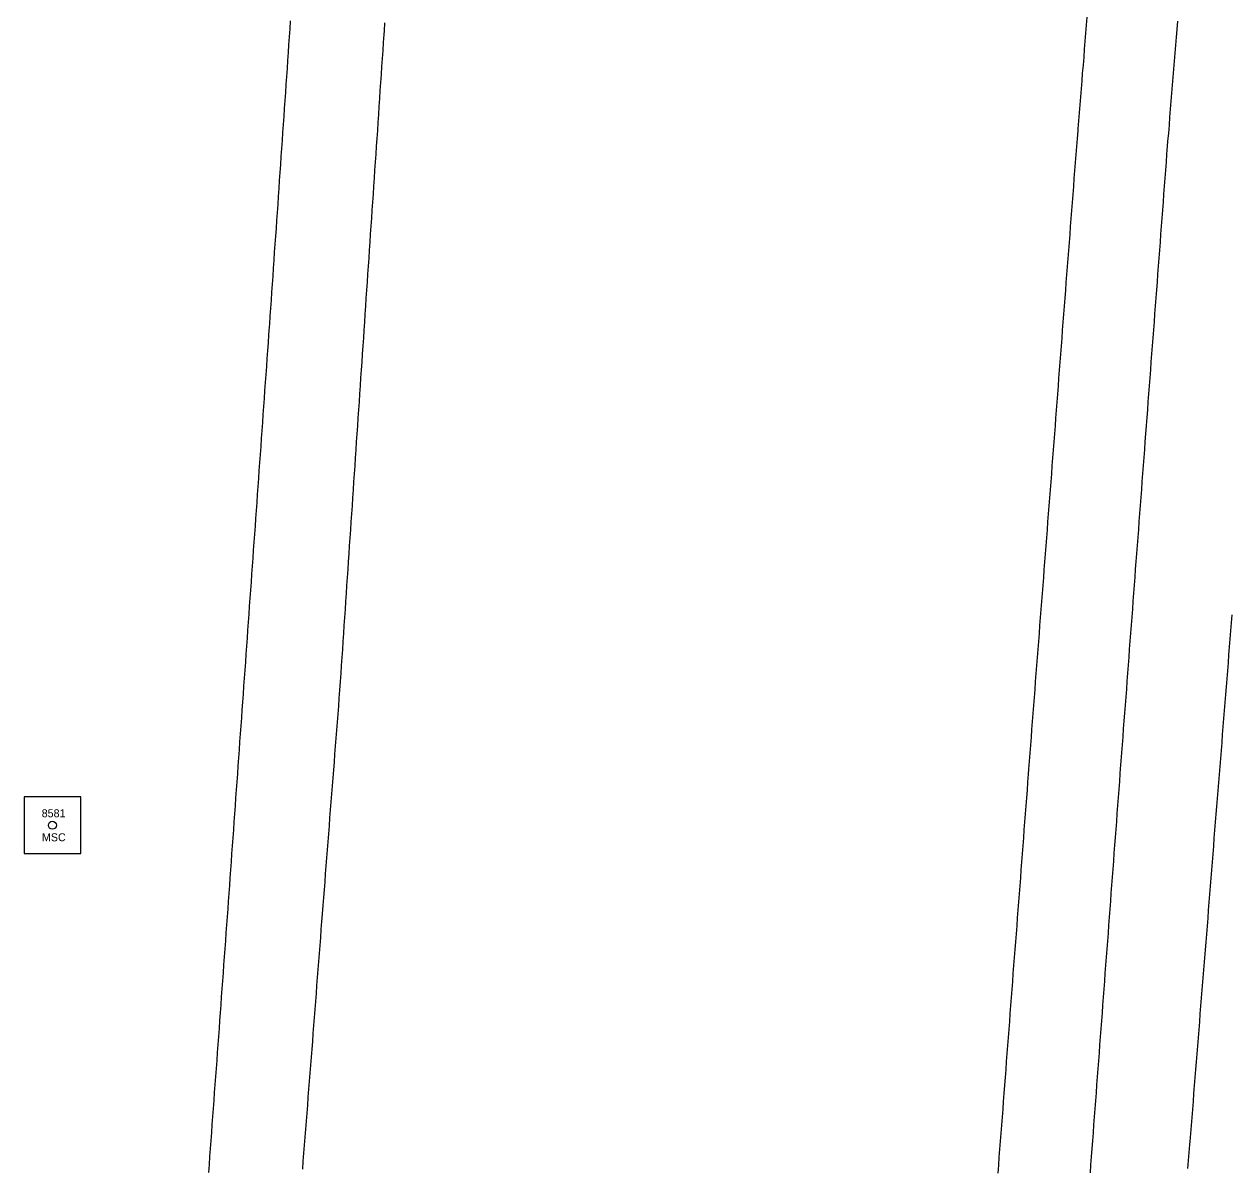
# Model space of a CAD drawing. Extents: x 205929 to 2357175, y -1785700 to 846739.
# Drawn here: x 2023418.4 to 2023569.3, y 809789.3 to 809932.1 of the extents above; entities that cross this region are included whole.
import ezdxf

# ---------------------------------------------------------------- set-up
doc = ezdxf.new("R2010")
doc.units = 0
for name, color, linetype in [('RD_HC_Survey', 7, 'Continuous'), ('RD_HC_txCode', 7, 'Continuous'), ('RD_Sketch1', 7, 'Continuous'), ('RD_SMD_Locator', 7, 'Continuous')]:
    doc.layers.add(name, color=color, linetype=linetype)

msp = doc.modelspace()

# ---------------------------------------------------------------- linework, layer by layer
at = {"layer": 'RD_HC_Survey'}
msp.add_lwpolyline([(2023425.5, 809835.58), (2023418.43, 809835.58), (2023418.43, 809828.51), (2023425.5, 809828.51)], close=True, dxfattribs=at)
msp.add_circle((2023421.96, 809832.04), 0.5, dxfattribs=at)
at = {"layer": 'RD_Sketch1'}
for points in [[(2023451.68, 809932.53), (2023451.61, 809931.53), (2023451.54, 809930.53), (2023451.47, 809929.53), (2023451.4, 809928.54), (2023451.34, 809927.54), (2023451.27, 809926.54), (2023451.2, 809925.54), (2023451.13, 809924.55), (2023451.06, 809923.55), (2023450.99, 809922.55), (2023450.92, 809921.55), (2023450.85, 809920.56), (2023450.78, 809919.56), (2023450.72, 809918.56), (2023450.65, 809917.56), (2023450.58, 809916.57), (2023450.58, 809916.57), (2023450.51, 809915.57), (2023450.44, 809914.57), (2023450.37, 809913.58), (2023450.3, 809912.58), (2023450.23, 809911.58), (2023450.16, 809910.58), (2023450.1, 809909.59), (2023450.03, 809908.59), (2023449.96, 809907.59), (2023449.89, 809906.59), (2023449.82, 809905.6), (2023449.75, 809904.6), (2023449.68, 809903.6), (2023449.61, 809902.6), (2023449.55, 809901.61), (2023449.48, 809900.61), (2023449.41, 809899.61), (2023449.34, 809898.61), (2023449.27, 809897.62), (2023449.2, 809896.62), (2023449.13, 809895.62), (2023449.06, 809894.62), (2023449.04, 809894.31), (2023448.97, 809893.31), (2023448.9, 809892.31), (2023448.83, 809891.32), (2023448.76, 809890.32), (2023448.69, 809889.32), (2023448.61, 809888.32), (2023448.54, 809887.33), (2023448.47, 809886.33), (2023448.4, 809885.33), (2023448.33, 809884.34), (2023448.26, 809883.34), (2023448.19, 809882.34), (2023448.12, 809881.34), (2023448.05, 809880.35), (2023447.98, 809879.35), (2023447.9, 809878.35), (2023447.83, 809877.35), (2023447.76, 809876.36), (2023447.69, 809875.36), (2023447.62, 809874.36), (2023447.55, 809873.36), (2023447.48, 809872.37), (2023447.41, 809871.37), (2023447.34, 809870.37), (2023447.27, 809869.38), (2023447.19, 809868.38), (2023447.12, 809867.38), (2023447.05, 809866.38), (2023446.98, 809865.39), (2023446.91, 809864.39), (2023446.84, 809863.39), (2023446.77, 809862.39), (2023446.7, 809861.4), (2023446.63, 809860.4), (2023446.55, 809859.4), (2023446.48, 809858.41), (2023446.41, 809857.41), (2023446.34, 809856.41), (2023446.27, 809855.41), (2023446.2, 809854.42), (2023446.13, 809853.42), (2023446.13, 809853.42), (2023446.06, 809852.42), (2023445.99, 809851.42), (2023445.92, 809850.43), (2023445.84, 809849.43), (2023445.77, 809848.43), (2023445.7, 809847.43), (2023445.63, 809846.44), (2023445.56, 809845.44), (2023445.49, 809844.44), (2023445.42, 809843.45), (2023445.35, 809842.45), (2023445.28, 809841.45), (2023445.2, 809840.45), (2023445.13, 809839.46), (2023445.06, 809838.46), (2023444.99, 809837.46), (2023444.92, 809836.46), (2023444.85, 809835.47), (2023444.78, 809834.47), (2023444.71, 809833.47), (2023444.64, 809832.47), (2023444.57, 809831.48), (2023444.49, 809830.48), (2023444.42, 809829.48), (2023444.35, 809828.49), (2023444.28, 809827.49), (2023444.21, 809826.49), (2023444.14, 809825.49), (2023444.07, 809824.5), (2023444, 809823.5), (2023443.93, 809822.5), (2023443.86, 809821.6), (2023443.79, 809820.6), (2023443.72, 809819.6), (2023443.64, 809818.61), (2023443.57, 809817.61), (2023443.5, 809816.61), (2023443.42, 809815.61), (2023443.35, 809814.62), (2023443.28, 809813.62), (2023443.21, 809812.62), (2023443.21, 809812.62), (2023443.13, 809811.62), (2023443.06, 809810.63), (2023442.99, 809809.63), (2023442.91, 809808.63), (2023442.84, 809807.64), (2023442.77, 809806.64), (2023442.69, 809805.64), (2023442.62, 809804.64), (2023442.55, 809803.65), (2023442.48, 809802.65), (2023442.4, 809801.65), (2023442.33, 809800.65), (2023442.26, 809799.66), (2023442.18, 809798.66), (2023442.11, 809797.66), (2023442.04, 809796.67), (2023441.96, 809795.67), (2023441.89, 809794.67), (2023441.82, 809793.67), (2023441.75, 809792.68), (2023441.67, 809791.68), (2023441.6, 809790.68), (2023441.53, 809789.68), (2023441.45, 809788.69)], [(2023463.45, 809932.28), (2023463.39, 809931.28), (2023463.35, 809930.8), (2023463.29, 809929.8), (2023463.22, 809928.81), (2023463.15, 809927.81), (2023463.09, 809926.81), (2023463.02, 809925.81), (2023462.95, 809924.82), (2023462.88, 809923.82), (2023462.82, 809922.82), (2023462.75, 809921.82), (2023462.68, 809920.83), (2023462.61, 809919.83), (2023462.55, 809918.83), (2023462.48, 809917.83), (2023462.41, 809916.84), (2023462.35, 809915.84), (2023462.28, 809914.84), (2023462.21, 809913.84), (2023462.14, 809912.85), (2023462.08, 809911.85), (2023462.01, 809910.85), (2023461.94, 809909.85), (2023461.87, 809908.86), (2023461.81, 809907.86), (2023461.74, 809906.86), (2023461.67, 809905.86), (2023461.61, 809904.87), (2023461.54, 809903.87), (2023461.47, 809902.87), (2023461.4, 809901.87), (2023461.34, 809900.88), (2023461.27, 809899.88), (2023461.2, 809898.88), (2023461.13, 809897.88), (2023461.07, 809896.89), (2023461, 809895.89), (2023460.93, 809894.89), (2023460.87, 809893.89), (2023460.8, 809892.9), (2023460.73, 809891.9), (2023460.66, 809890.9), (2023460.6, 809889.9), (2023460.53, 809888.91), (2023460.53, 809888.91), (2023460.46, 809887.91), (2023460.39, 809886.91), (2023460.33, 809885.91), (2023460.26, 809884.92), (2023460.19, 809883.92), (2023460.13, 809882.92), (2023460.06, 809881.92), (2023459.99, 809880.93), (2023459.92, 809879.93), (2023459.86, 809878.93), (2023459.79, 809877.93), (2023459.72, 809876.94), (2023459.66, 809875.94), (2023459.59, 809874.94), (2023459.52, 809873.94), (2023459.45, 809872.95), (2023459.39, 809871.95), (2023459.32, 809870.95), (2023459.25, 809869.95), (2023459.18, 809868.96), (2023459.12, 809867.96), (2023459.05, 809866.96), (2023458.98, 809865.96), (2023458.92, 809864.97), (2023458.85, 809863.97), (2023458.78, 809862.97), (2023458.71, 809861.97), (2023458.65, 809860.98), (2023458.58, 809859.98), (2023458.51, 809858.98), (2023458.44, 809857.98), (2023458.38, 809856.99), (2023458.31, 809855.99), (2023458.24, 809854.99), (2023458.18, 809853.99), (2023458.11, 809853), (2023458.04, 809852), (2023457.97, 809851), (2023457.91, 809850), (2023457.83, 809848.91), (2023457.76, 809847.92), (2023457.68, 809846.92), (2023457.6, 809845.92), (2023457.52, 809844.93), (2023457.45, 809843.93), (2023457.37, 809842.93), (2023457.29, 809841.94), (2023457.21, 809840.94), (2023457.14, 809839.94), (2023457.06, 809838.95), (2023456.98, 809837.95), (2023456.9, 809836.95), (2023456.83, 809835.96), (2023456.75, 809834.96), (2023456.67, 809833.96), (2023456.59, 809832.96), (2023456.52, 809831.97), (2023456.44, 809830.97), (2023456.36, 809829.97), (2023456.28, 809828.98), (2023456.21, 809827.98), (2023456.13, 809826.98), (2023456.05, 809825.99), (2023455.97, 809824.99), (2023455.97, 809824.99), (2023455.9, 809823.99), (2023455.82, 809823), (2023455.74, 809822), (2023455.67, 809821), (2023455.59, 809820.01), (2023455.51, 809819.01), (2023455.43, 809818.01), (2023455.36, 809817.02), (2023455.28, 809816.02), (2023455.2, 809815.02), (2023455.12, 809814.02), (2023455.05, 809813.03), (2023454.97, 809812.03), (2023454.89, 809811.03), (2023454.81, 809810.04), (2023454.74, 809809.04), (2023454.66, 809808.04), (2023454.58, 809807.05), (2023454.5, 809806.05), (2023454.43, 809805.05), (2023454.35, 809804.06), (2023454.27, 809803.06), (2023454.19, 809802.06), (2023454.12, 809801.07), (2023454.04, 809800.07), (2023453.96, 809799.07), (2023453.88, 809798.08), (2023453.81, 809797.08), (2023453.73, 809796.08), (2023453.65, 809795.08), (2023453.57, 809794.09), (2023453.5, 809793.09), (2023453.42, 809792.09), (2023453.34, 809791.1), (2023453.26, 809790.1), (2023453.19, 809789.1)], [(2023551.19, 809932.97), (2023551.11, 809931.97), (2023551.03, 809930.97), (2023550.95, 809929.98), (2023550.87, 809928.98), (2023550.79, 809927.98), (2023550.71, 809926.99), (2023550.62, 809925.99), (2023550.54, 809925), (2023550.46, 809924), (2023550.38, 809923), (2023550.3, 809922.01), (2023550.22, 809921.01), (2023550.14, 809920.01), (2023550.06, 809919.02), (2023550.04, 809918.79), (2023549.96, 809917.8), (2023549.89, 809916.8), (2023549.81, 809915.8), (2023549.73, 809914.8), (2023549.66, 809913.81), (2023549.58, 809912.81), (2023549.5, 809911.81), (2023549.43, 809910.82), (2023549.35, 809909.82), (2023549.27, 809908.82), (2023549.2, 809907.83), (2023549.12, 809906.83), (2023549.04, 809905.83), (2023548.97, 809904.84), (2023548.89, 809903.84), (2023548.81, 809902.84), (2023548.74, 809901.84), (2023548.66, 809900.85), (2023548.58, 809899.85), (2023548.51, 809898.85), (2023548.43, 809897.86), (2023548.35, 809896.86), (2023548.28, 809895.86), (2023548.2, 809894.87), (2023548.12, 809893.87), (2023548.05, 809892.87), (2023547.97, 809891.88), (2023547.97, 809891.88), (2023547.89, 809890.88), (2023547.82, 809889.88), (2023547.74, 809888.88), (2023547.66, 809887.89), (2023547.59, 809886.89), (2023547.51, 809885.89), (2023547.43, 809884.9), (2023547.36, 809883.9), (2023547.28, 809882.9), (2023547.21, 809881.91), (2023547.13, 809880.91), (2023547.05, 809879.91), (2023546.98, 809878.92), (2023546.9, 809877.92), (2023546.82, 809876.92), (2023546.75, 809875.92), (2023546.67, 809874.93), (2023546.59, 809873.93), (2023546.52, 809872.93), (2023546.44, 809871.94), (2023546.36, 809870.94), (2023546.29, 809869.94), (2023546.21, 809868.95), (2023546.13, 809867.95), (2023546.06, 809866.95), (2023545.98, 809865.96), (2023545.9, 809864.96), (2023545.83, 809863.96), (2023545.75, 809862.97), (2023545.67, 809861.97), (2023545.6, 809860.97), (2023545.52, 809859.97), (2023545.44, 809858.98), (2023545.37, 809857.98), (2023545.29, 809856.98), (2023545.21, 809855.99), (2023545.14, 809854.99), (2023545.06, 809853.99), (2023544.98, 809853), (2023544.91, 809852), (2023544.83, 809851), (2023544.75, 809850.01), (2023544.68, 809849.01), (2023544.6, 809848.01), (2023544.52, 809847.01), (2023544.45, 809846.02), (2023544.37, 809845.02), (2023544.29, 809844.02), (2023544.22, 809843.03), (2023544.14, 809842.03), (2023544.06, 809841.03), (2023543.99, 809840.04), (2023543.91, 809839.04), (2023543.86, 809838.44), (2023543.79, 809837.44), (2023543.71, 809836.44), (2023543.64, 809835.45), (2023543.56, 809834.45), (2023543.48, 809833.45), (2023543.41, 809832.46), (2023543.33, 809831.46), (2023543.26, 809830.46), (2023543.18, 809829.47), (2023543.1, 809828.47), (2023543.1, 809828.47), (2023543.03, 809827.47), (2023542.95, 809826.48), (2023542.88, 809825.48), (2023542.8, 809824.48), (2023542.72, 809823.48), (2023542.65, 809822.49), (2023542.57, 809821.49), (2023542.49, 809820.49), (2023542.42, 809819.5), (2023542.34, 809818.5), (2023542.27, 809817.5), (2023542.19, 809816.51), (2023542.11, 809815.51), (2023542.04, 809814.51), (2023541.96, 809813.52), (2023541.89, 809812.52), (2023541.81, 809811.52), (2023541.73, 809810.52), (2023541.66, 809809.53), (2023541.58, 809808.53), (2023541.51, 809807.53), (2023541.43, 809806.54), (2023541.35, 809805.54), (2023541.28, 809804.54), (2023541.2, 809803.55), (2023541.12, 809802.55), (2023541.05, 809801.55), (2023540.97, 809800.55), (2023540.9, 809799.56), (2023540.82, 809798.56), (2023540.74, 809797.56), (2023540.67, 809796.57), (2023540.59, 809795.57), (2023540.52, 809794.57), (2023540.52, 809794.57), (2023540.44, 809793.58), (2023540.36, 809792.58), (2023540.29, 809791.58), (2023540.21, 809790.59), (2023540.14, 809789.59), (2023540.06, 809788.59)], [(2023562.51, 809932.45), (2023562.43, 809931.45), (2023562.35, 809930.46), (2023562.26, 809929.46), (2023562.18, 809928.46), (2023562.1, 809927.47), (2023562.02, 809926.47), (2023561.94, 809925.47), (2023561.86, 809924.48), (2023561.77, 809923.48), (2023561.69, 809922.49), (2023561.61, 809921.49), (2023561.53, 809920.49), (2023561.45, 809919.5), (2023561.37, 809918.5), (2023561.28, 809917.5), (2023561.23, 809916.84), (2023561.15, 809915.84), (2023561.08, 809914.85), (2023561, 809913.85), (2023560.93, 809912.85), (2023560.85, 809911.86), (2023560.78, 809910.86), (2023560.7, 809909.86), (2023560.63, 809908.87), (2023560.55, 809907.87), (2023560.48, 809906.87), (2023560.4, 809905.87), (2023560.33, 809904.88), (2023560.25, 809903.88), (2023560.18, 809902.88), (2023560.1, 809901.89), (2023560.03, 809900.89), (2023559.95, 809899.89), (2023559.88, 809898.9), (2023559.8, 809897.9), (2023559.73, 809896.9), (2023559.65, 809895.91), (2023559.58, 809894.91), (2023559.5, 809893.91), (2023559.42, 809892.92), (2023559.35, 809891.92), (2023559.35, 809891.92), (2023559.27, 809890.92), (2023559.2, 809889.92), (2023559.12, 809888.93), (2023559.05, 809887.93), (2023558.97, 809886.93), (2023558.9, 809885.94), (2023558.82, 809884.94), (2023558.75, 809883.94), (2023558.67, 809882.95), (2023558.6, 809881.95), (2023558.52, 809880.95), (2023558.45, 809879.96), (2023558.37, 809878.96), (2023558.3, 809877.96), (2023558.22, 809876.97), (2023558.15, 809875.97), (2023558.07, 809874.97), (2023558, 809873.97), (2023557.92, 809872.98), (2023557.85, 809871.98), (2023557.77, 809870.98), (2023557.7, 809869.99), (2023557.62, 809868.99), (2023557.55, 809867.99), (2023557.47, 809867), (2023557.39, 809866), (2023557.32, 809865), (2023557.24, 809864.01), (2023557.17, 809863.01), (2023557.09, 809862.01), (2023557.02, 809861.02), (2023556.94, 809860.02), (2023556.87, 809859.02), (2023556.79, 809858.03), (2023556.72, 809857.03), (2023556.64, 809856.03), (2023556.57, 809855.03), (2023556.49, 809854.04), (2023556.42, 809853.04), (2023556.34, 809852.04), (2023556.27, 809851.05), (2023556.19, 809850.05), (2023556.12, 809849.05), (2023556.04, 809848.06), (2023555.97, 809847.06), (2023555.89, 809846.06), (2023555.82, 809845.07), (2023555.74, 809844.07), (2023555.67, 809843.07), (2023555.59, 809842.08), (2023555.52, 809841.08), (2023555.44, 809840.08), (2023555.36, 809839.08), (2023555.32, 809838.51), (2023555.25, 809837.51), (2023555.17, 809836.52), (2023555.1, 809835.52), (2023555.02, 809834.52), (2023554.95, 809833.52), (2023554.87, 809832.53), (2023554.8, 809831.53), (2023554.72, 809830.53), (2023554.65, 809829.54), (2023554.57, 809828.54), (2023554.57, 809828.54), (2023554.5, 809827.54), (2023554.42, 809826.54), (2023554.35, 809825.55), (2023554.27, 809824.55), (2023554.2, 809823.55), (2023554.13, 809822.56), (2023554.05, 809821.56), (2023553.98, 809820.56), (2023553.9, 809819.56), (2023553.83, 809818.57), (2023553.75, 809817.57), (2023553.68, 809816.57), (2023553.6, 809815.58), (2023553.53, 809814.58), (2023553.45, 809813.58), (2023553.38, 809812.58), (2023553.3, 809811.59), (2023553.23, 809810.59), (2023553.15, 809809.59), (2023553.08, 809808.6), (2023553, 809807.6), (2023552.93, 809806.6), (2023552.85, 809805.6), (2023552.78, 809804.61), (2023552.71, 809803.61), (2023552.63, 809802.61), (2023552.56, 809801.62), (2023552.48, 809800.62), (2023552.41, 809799.62), (2023552.33, 809798.62), (2023552.26, 809797.63), (2023552.18, 809796.63), (2023552.11, 809795.63), (2023552.03, 809794.64), (2023551.96, 809793.64), (2023551.88, 809792.64), (2023551.81, 809791.65), (2023551.73, 809790.65), (2023551.66, 809789.65), (2023551.58, 809788.65)], [(2023569.3, 809858.32), (2023569.22, 809857.33), (2023569.14, 809856.33), (2023569.06, 809855.33), (2023568.98, 809854.34), (2023568.9, 809853.34), (2023568.83, 809852.34), (2023568.75, 809851.35), (2023568.67, 809850.35), (2023568.59, 809849.35), (2023568.51, 809848.36), (2023568.43, 809847.36), (2023568.35, 809846.36), (2023568.27, 809845.37), (2023568.19, 809844.37), (2023568.11, 809843.37), (2023568.03, 809842.38), (2023567.95, 809841.38), (2023567.87, 809840.38), (2023567.79, 809839.39), (2023567.71, 809838.39), (2023567.63, 809837.39), (2023567.55, 809836.4), (2023567.47, 809835.4), (2023567.39, 809834.4), (2023567.31, 809833.41), (2023567.23, 809832.41), (2023567.15, 809831.41), (2023567.07, 809830.42), (2023566.99, 809829.42), (2023566.92, 809828.42), (2023566.84, 809827.43), (2023566.76, 809826.43), (2023566.68, 809825.43), (2023566.6, 809824.44), (2023566.52, 809823.44), (2023566.44, 809822.45), (2023566.36, 809821.45), (2023566.28, 809820.45), (2023566.2, 809819.46), (2023566.12, 809818.46), (2023566.04, 809817.46), (2023565.96, 809816.47), (2023565.88, 809815.47), (2023565.8, 809814.47), (2023565.72, 809813.48), (2023565.64, 809812.48), (2023565.56, 809811.48), (2023565.48, 809810.49), (2023565.4, 809809.49), (2023565.32, 809808.49), (2023565.24, 809807.5), (2023565.16, 809806.5), (2023565.09, 809805.5), (2023565.01, 809804.51), (2023564.93, 809803.51), (2023564.85, 809802.51), (2023564.77, 809801.52), (2023564.69, 809800.52), (2023564.61, 809799.52), (2023564.53, 809798.53), (2023564.45, 809797.53), (2023564.37, 809796.53), (2023564.29, 809795.54), (2023564.21, 809794.54), (2023564.21, 809794.54), (2023564.13, 809793.54), (2023564.05, 809792.55), (2023564.02, 809792.17), (2023563.94, 809791.17), (2023563.86, 809790.18), (2023563.78, 809789.18)]]:
    msp.add_lwpolyline(points, dxfattribs=at)
at = {"layer": 'RD_SMD_Locator'}
msp.add_circle((2023421.96, 809832.04), 0.001, dxfattribs=at)

# ---------------------------------------------------------------- texts
at = {"layer": 'RD_HC_txCode'}
for s, p in [('8581', (2023420.62, 809833.04)), ('MSC', (2023420.65, 809830.04))]:
    msp.add_text(s, height=1, dxfattribs=at).set_placement(p)

doc.saveas('drawing.dxf')
